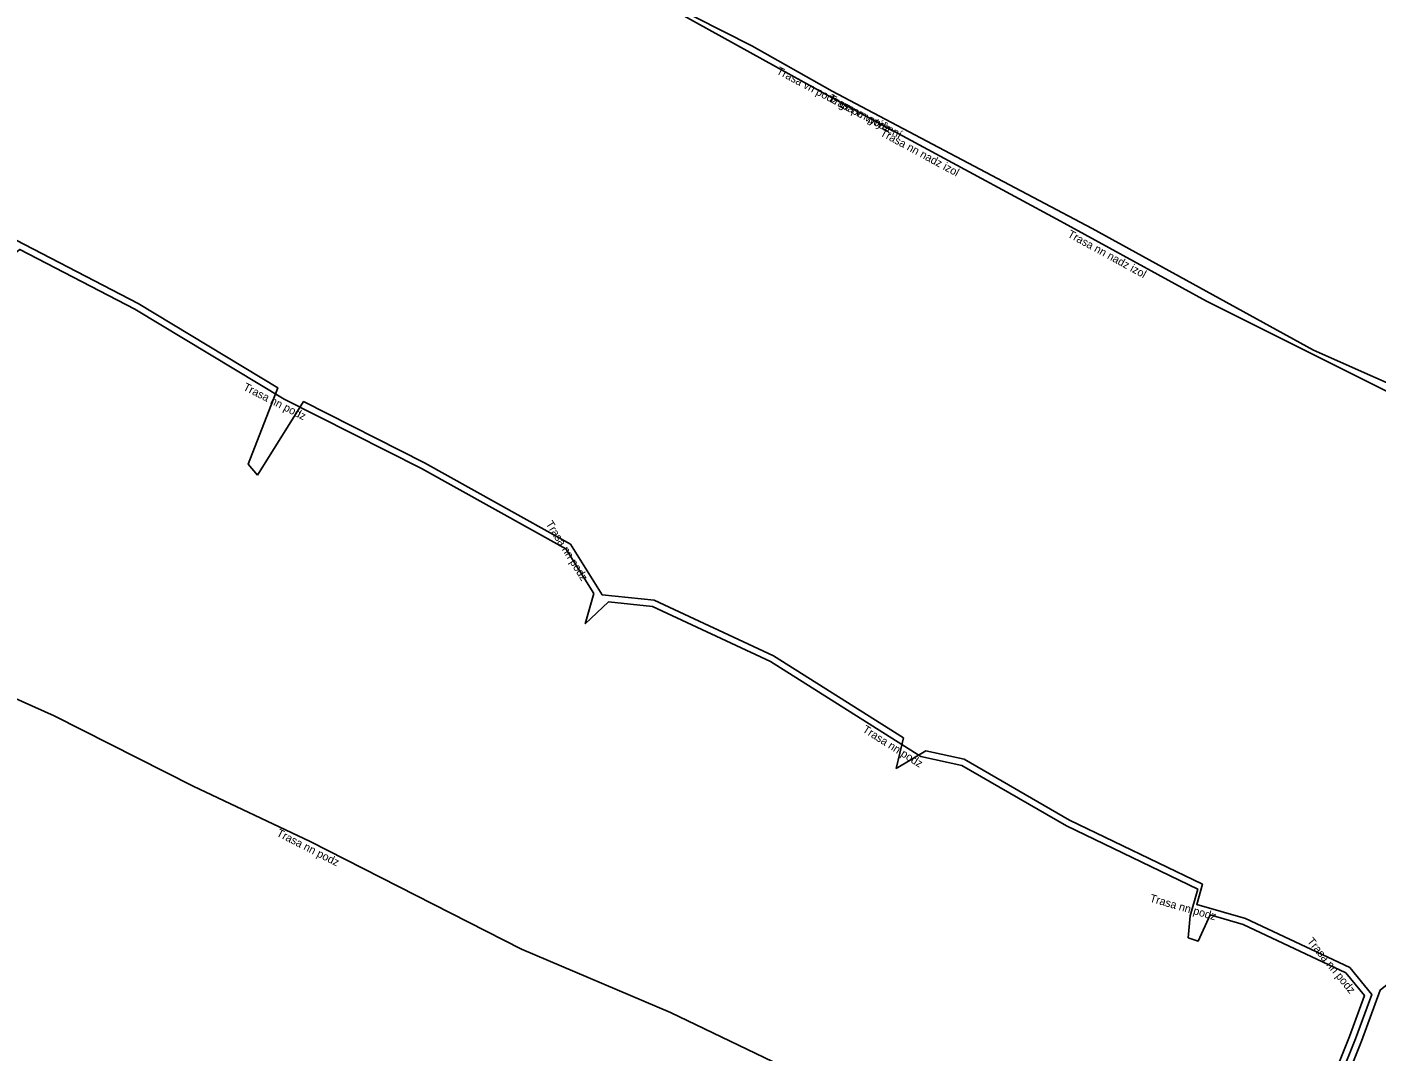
# Model space of a CAD drawing. Extents: x -528089 to -527692, y -1079306 to -1078676.
# Drawn here: x -528006 to -527921.7, y -1079080.7 to -1079016.7 of the extents above; entities that cross this region are included whole.
import ezdxf

# ---------------------------------------------------------------- set-up
doc = ezdxf.new("R2010")
doc.units = 0
for name, color, linetype in [('Popiskový text - Ostatní atributy Trasy', 7, 'Continuous'), ('Spojnice NN', 7, 'Continuous'), ('Spojnice VN', 7, 'Continuous')]:
    doc.layers.add(name, color=color, linetype=linetype)

msp = doc.modelspace()

# ---------------------------------------------------------------- linework, layer by layer
at = {"layer": 'Spojnice NN'}
for points in [[(-527991.703, -1079001.194), (-527955.651, -1079021.133)], [(-527991.56, -1079044.709), (-527992.14, -1079044.02), (-527990.287, -1079039.251), (-527999.022, -1079033.985), (-528007.772, -1079029.457), (-528008.388, -1079027.191), (-528016.21, -1079022.376), (-528023.357, -1079018.571), (-528025.835, -1079018.497), (-528029.322, -1079022.24), (-528037.639, -1079036.693), (-528037.392, -1079038.118), (-528034.126, -1079040.313), (-528030.747, -1079041.751)], [(-527955.651, -1079021.133), (-527941.396, -1079028.841)], [(-527941.396, -1079028.841), (-527932.259, -1079033.84)], [(-527971.08, -1079054.01), (-527970.552, -1079052.101), (-527972.292, -1079049.32), (-527981.304, -1079044.307), (-527989.884, -1079039.96), (-527999.218, -1079034.335), (-528006.408, -1079030.613), (-528007.91, -1079031.73), (-528009.93, -1079034.249)], [(-527932.259, -1079033.84), (-527902.433, -1079048.76)], [(-527951.65, -1079063.04), (-527951.19, -1079061.134), (-527959.314, -1079056.004), (-527966.766, -1079052.524), (-527970.018, -1079052.202), (-527972.008, -1079049.02), (-527981.116, -1079043.953), (-527988.683, -1079040.12), (-527991.56, -1079044.709)], [(-528038.839, -1079070.187), (-528033.707, -1079071.493), (-528030.406, -1079064.778), (-528028.232, -1079060.171), (-528022.792, -1079050.226), (-528016.804, -1079053.755), (-528010.474, -1079056.989), (-528004.254, -1079059.749), (-527995.582, -1079064.16), (-527988.262, -1079067.6), (-527975.065, -1079074.339), (-527965.758, -1079078.298), (-527957.785, -1079082.119), (-527950.557, -1079085.484), (-527943.448, -1079086.314), (-527938.096, -1079087.991), (-527929.424, -1079091.182), (-527928.678, -1079089.783), (-527927.427, -1079087.702), (-527927.381, -1079085.446)], [(-527933.42, -1079073.63), (-527933.29, -1079072.26), (-527932.815, -1079070.585), (-527941.014, -1079066.637), (-527947.543, -1079062.849), (-527950.103, -1079062.295), (-527959.506, -1079056.356), (-527966.874, -1079052.916), (-527969.632, -1079052.642), (-527971.08, -1079054.01)], [(-527927.381, -1079085.446), (-527924.837, -1079084.61), (-527922.96, -1079079.93), (-527921.94, -1079077.162), (-527923.314, -1079075.488), (-527929.839, -1079072.412), (-527932.878, -1079071.538), (-527932.522, -1079070.283), (-527940.826, -1079066.283), (-527947.397, -1079062.471), (-527949.807, -1079061.95), (-527951.65, -1079063.04)], [(-527912.78, -1079069.674), (-527913.15, -1079070.02), (-527917.1, -1079073.42), (-527921.413, -1079076.892), (-527922.586, -1079080.074), (-527924.86, -1079085.77), (-527925.354, -1079085.808), (-527927.982, -1079090.177), (-527929.045, -1079092.173), (-527929.487, -1079092.011), (-527931.27, -1079094.63), (-527929.212, -1079098.88), (-527928.094, -1079103.067), (-527930.429, -1079103.322)], [(-527927.381, -1079085.446), (-527925.041, -1079084.061), (-527923.334, -1079079.786), (-527922.395, -1079077.239), (-527923.566, -1079075.812), (-527929.981, -1079072.788), (-527932.043, -1079072.194), (-527932.79, -1079073.84), (-527933.42, -1079073.63)]]:
    msp.add_lwpolyline(points, dxfattribs=at)
at = {"layer": 'Spojnice VN'}
msp.add_lwpolyline([(-527900.67, -1079080.75), (-527902.31, -1079079.5), (-527906.63, -1079073.48), (-527905.99, -1079070.78), (-527898.71, -1079055.64), (-527897.08, -1079052.2), (-527897.4, -1079050.06), (-527898.22, -1079048.86), (-527902.3, -1079046.36), (-527913.68, -1079040.68), (-527917.97, -1079040.28), (-527925.59, -1079036.9), (-527939.41, -1079029.3), (-527955.66, -1079020.73), (-527960.68, -1079017.89), (-527978.24, -1079008.97), (-527990.68, -1079001.77), (-528000.14, -1078996.92), (-528007.17, -1078993.13)], dxfattribs=at)
msp.add_lwpolyline([(-527900.67, -1079080.75), (-527902.31, -1079079.5), (-527906.63, -1079073.48), (-527905.99, -1079070.78), (-527898.71, -1079055.64), (-527897.08, -1079052.2), (-527897.4, -1079050.06), (-527898.22, -1079048.86), (-527902.3, -1079046.36), (-527913.68, -1079040.68), (-527917.97, -1079040.28), (-527925.59, -1079036.9), (-527939.41, -1079029.3), (-527955.66, -1079020.73), (-527960.68, -1079017.89), (-527978.24, -1079008.97), (-527990.68, -1079001.77), (-528000.14, -1078996.92), (-528007.17, -1078993.13)], dxfattribs=at)

# ---------------------------------------------------------------- texts
at = {"layer": 'Popiskový text - Ostatní atributy Trasy'}
for s, rotation, p in [('Trasa vn podz gz po vytýèení', 332.19353, (-527959.176, -1079019.611)), ('Trasa vn podz', 332.19353, (-527955.917, -1079021.33)), ('Trasa nn nadz izol', 331.59796, (-527952.694, -1079023.471)), ('Trasa nn nadz izol', 331.31545, (-527940.99, -1079029.804)), ('Trasa nn podz', 333.13125, (-527992.496, -1079039.365)), ('Trasa nn podz', 302.02157, (-527973.567, -1079047.753)), ('Trasa nn podz', 327.72321, (-527953.801, -1079060.728)), ('Trasa nn podz', 332.94904, (-527990.411, -1079067.232)), ('Trasa nn podz', 343.95505, (-527935.849, -1079071.36)), ('Trasa nn podz', 309.37239, (-527926.01, -1079073.858))]:
    msp.add_text(s, height=0.5, rotation=rotation, dxfattribs=at).set_placement(p)

doc.saveas('drawing.dxf')
